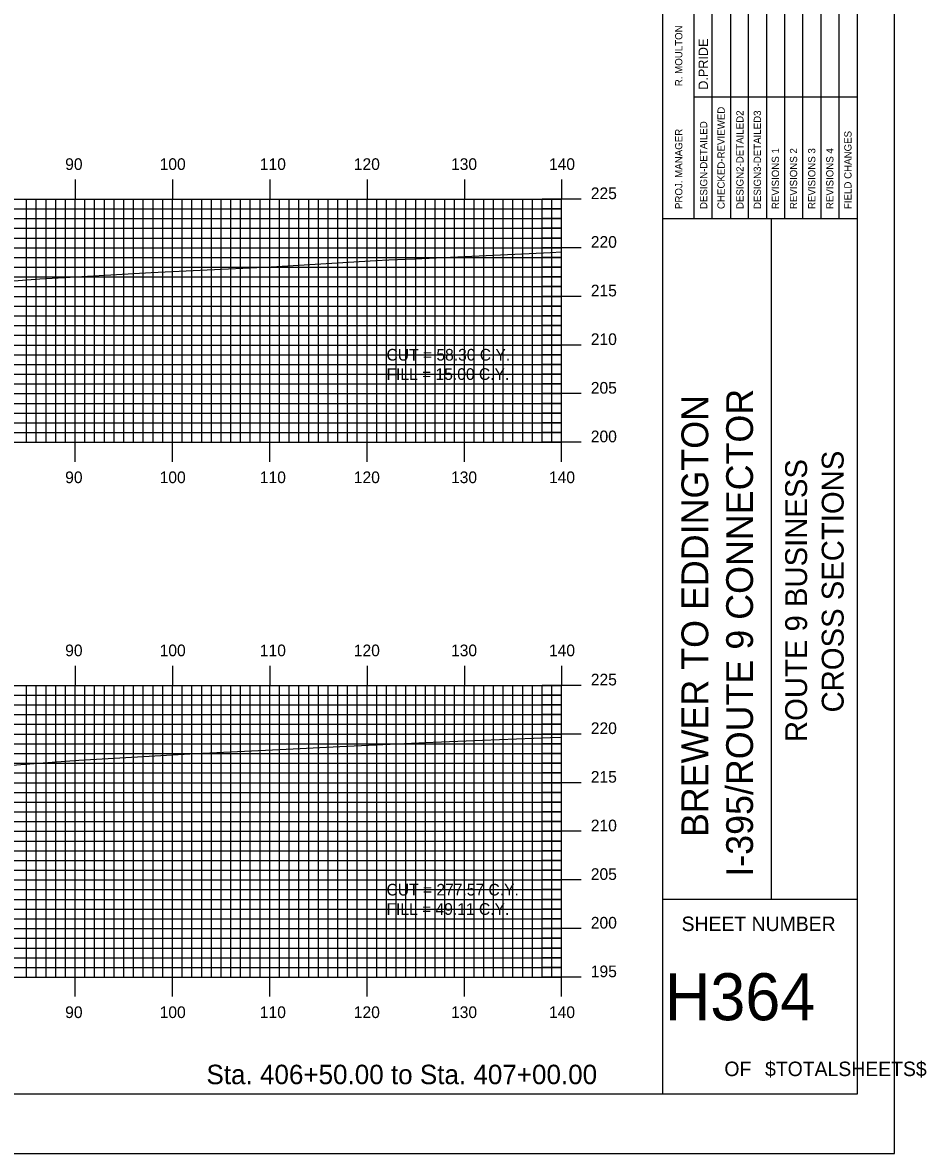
# Model space of a CAD drawing. Extents: x 852135 to 852479, y 364785 to 365005.
# Drawn here: x 852385.8 to 852478.7, y 364785.1 to 364901.4 of the extents above; entities that cross this region are included whole.
import ezdxf

# ---------------------------------------------------------------- set-up
doc = ezdxf.new("R2010")
doc.units = 0
for name, color, linetype in [('BORDER', 7, 'Continuous'), ('D_Text_Standard', 7, 'Continuous'), ('H_V ANNOTATION', 7, 'Continuous'), ('MAJOR', 7, 'Continuous'), ('MINOR', 7, 'Continuous'), ('PLOT BOUNDARY', 7, 'Continuous'), ('S_Roadway_Centerline', 7, 'Continuous')]:
    doc.layers.add(name, color=color, linetype=linetype)

msp = doc.modelspace()

# ---------------------------------------------------------------- linework, layer by layer
at = {"layer": 'BORDER'}
for p, q in [((852451.62, 364791.23), (852451.62, 365001.23)), ((852451.62, 364881.24), (852471.62, 364881.24)), ((852462.8, 364811.24), (852462.8, 364881.24)), ((852451.62, 364811.24), (852471.62, 364811.24))]:
    msp.add_line(p, q, dxfattribs=at)
msp.add_lwpolyline([(852151.62, 364791.23), (852471.62, 364791.23), (852471.62, 365001.23), (852151.62, 365001.23)], close=True, dxfattribs=at)
for points in [[(852456.71, 364881.24), (852456.71, 364916.24)], [(852458.58, 364916.24), (852458.58, 364881.24)], [(852460.44, 364881.24), (852460.44, 364916.24)], [(852462.3, 364881.24), (852462.3, 364916.24)], [(852464.17, 364881.24), (852464.17, 364916.24)], [(852466.03, 364881.24), (852466.03, 364916.24)], [(852467.89, 364881.24), (852467.89, 364916.24)], [(852469.76, 364881.24), (852469.76, 364916.24)], [(852454.85, 364881.24), (852454.85, 364914.83)], [(852454.85, 364893.74), (852471.62, 364893.74)]]:
    msp.add_lwpolyline(points, dxfattribs=at)
at = {"layer": 'MAJOR'}
for p, q in [((852391.22, 364885.24), (852391.22, 364883.23)), ((852401.22, 364885.24), (852401.22, 364883.23)), ((852411.22, 364885.24), (852411.22, 364883.23)), ((852421.22, 364885.24), (852421.22, 364883.23)), ((852431.22, 364885.24), (852431.22, 364883.23)), ((852441.22, 364885.24), (852441.22, 364883.23)), ((852301.22, 364883.23), (852441.22, 364883.23)), ((852301.22, 364883.23), (852441.22, 364883.23)), ((852391.22, 364858.23), (852391.22, 364883.23)), ((852401.22, 364858.23), (852401.22, 364883.23)), ((852411.22, 364858.23), (852411.22, 364883.23)), ((852421.22, 364858.23), (852421.22, 364883.23)), ((852431.22, 364858.23), (852431.22, 364883.23)), ((852443.22, 364883.23), (852439.21, 364883.23)), ((852441.22, 364858.23), (852441.22, 364883.23)), ((852441.22, 364858.23), (852441.22, 364883.23)), ((852301.22, 364878.23), (852441.22, 364878.23)), ((852443.22, 364878.23), (852439.21, 364878.23)), ((852301.22, 364873.23), (852441.22, 364873.23)), ((852443.22, 364873.23), (852439.21, 364873.23)), ((852301.22, 364868.23), (852441.22, 364868.23)), ((852443.22, 364868.23), (852439.21, 364868.23)), ((852301.22, 364863.23), (852441.22, 364863.23)), ((852443.22, 364863.23), (852439.21, 364863.23)), ((852301.22, 364858.23), (852441.22, 364858.23)), ((852301.22, 364858.23), (852441.22, 364858.23)), ((852391.22, 364856.23), (852391.22, 364858.23)), ((852401.22, 364856.23), (852401.22, 364858.23)), ((852411.22, 364856.23), (852411.22, 364858.23)), ((852421.22, 364856.23), (852421.22, 364858.23)), ((852431.22, 364856.23), (852431.22, 364858.23)), ((852443.22, 364858.23), (852439.21, 364858.23)), ((852441.22, 364856.23), (852441.22, 364858.23)), ((852391.22, 364835.24), (852391.22, 364833.23)), ((852401.22, 364835.24), (852401.22, 364833.23)), ((852411.22, 364835.24), (852411.22, 364833.23)), ((852421.22, 364835.24), (852421.22, 364833.23)), ((852431.22, 364835.24), (852431.22, 364833.23)), ((852441.22, 364835.24), (852441.22, 364833.23)), ((852161.22, 364833.23), (852441.22, 364833.23)), ((852161.22, 364833.23), (852441.22, 364833.23)), ((852391.22, 364803.23), (852391.22, 364833.23)), ((852401.22, 364803.23), (852401.22, 364833.23)), ((852411.22, 364803.23), (852411.22, 364833.23)), ((852421.22, 364803.23), (852421.22, 364833.23)), ((852431.22, 364803.23), (852431.22, 364833.23)), ((852443.22, 364833.23), (852439.21, 364833.23)), ((852441.22, 364803.23), (852441.22, 364833.23)), ((852441.22, 364803.23), (852441.22, 364833.23)), ((852161.22, 364828.23), (852441.22, 364828.23)), ((852443.22, 364828.23), (852439.21, 364828.23)), ((852161.22, 364823.23), (852441.22, 364823.23)), ((852443.22, 364823.23), (852439.21, 364823.23)), ((852161.22, 364818.23), (852441.22, 364818.23)), ((852443.22, 364818.23), (852439.21, 364818.23)), ((852161.22, 364813.23), (852441.22, 364813.23)), ((852443.22, 364813.23), (852439.21, 364813.23)), ((852161.22, 364808.23), (852441.22, 364808.23)), ((852443.22, 364808.23), (852439.21, 364808.23)), ((852161.22, 364803.23), (852441.22, 364803.23)), ((852161.22, 364803.23), (852441.22, 364803.23)), ((852391.22, 364801.23), (852391.22, 364803.23)), ((852401.22, 364801.23), (852401.22, 364803.23)), ((852411.22, 364801.23), (852411.22, 364803.23)), ((852421.22, 364801.23), (852421.22, 364803.23)), ((852431.22, 364801.23), (852431.22, 364803.23)), ((852443.22, 364803.23), (852439.21, 364803.23)), ((852441.22, 364801.23), (852441.22, 364803.23))]:
    msp.add_line(p, q, dxfattribs=at)
at = {"layer": 'MINOR'}
for p, q in [((852386.22, 364858.23), (852386.22, 364883.23)), ((852387.22, 364858.23), (852387.22, 364883.23)), ((852388.22, 364858.23), (852388.22, 364883.23)), ((852389.22, 364858.23), (852389.22, 364883.23)), ((852390.22, 364858.23), (852390.22, 364883.23)), ((852392.22, 364858.23), (852392.22, 364883.23)), ((852393.22, 364858.23), (852393.22, 364883.23)), ((852394.22, 364858.23), (852394.22, 364883.23)), ((852395.22, 364858.23), (852395.22, 364883.23)), ((852396.22, 364858.23), (852396.22, 364883.23)), ((852397.22, 364858.23), (852397.22, 364883.23)), ((852398.22, 364858.23), (852398.22, 364883.23)), ((852399.22, 364858.23), (852399.22, 364883.23)), ((852400.22, 364858.23), (852400.22, 364883.23)), ((852402.22, 364858.23), (852402.22, 364883.23)), ((852403.22, 364858.23), (852403.22, 364883.23)), ((852404.22, 364858.23), (852404.22, 364883.23)), ((852405.22, 364858.23), (852405.22, 364883.23)), ((852406.22, 364858.23), (852406.22, 364883.23)), ((852407.22, 364858.23), (852407.22, 364883.23)), ((852408.22, 364858.23), (852408.22, 364883.23)), ((852409.22, 364858.23), (852409.22, 364883.23)), ((852410.22, 364858.23), (852410.22, 364883.23)), ((852412.22, 364858.23), (852412.22, 364883.23)), ((852413.22, 364858.23), (852413.22, 364883.23)), ((852414.22, 364858.23), (852414.22, 364883.23)), ((852415.22, 364858.23), (852415.22, 364883.23)), ((852416.22, 364858.23), (852416.22, 364883.23)), ((852417.22, 364858.23), (852417.22, 364883.23)), ((852418.22, 364858.23), (852418.22, 364883.23)), ((852419.22, 364858.23), (852419.22, 364883.23)), ((852420.22, 364858.23), (852420.22, 364883.23)), ((852422.22, 364858.23), (852422.22, 364883.23)), ((852423.22, 364858.23), (852423.22, 364883.23)), ((852424.22, 364858.23), (852424.22, 364883.23)), ((852425.22, 364858.23), (852425.22, 364883.23)), ((852426.22, 364858.23), (852426.22, 364883.23)), ((852427.22, 364858.23), (852427.22, 364883.23)), ((852428.22, 364858.23), (852428.22, 364883.23)), ((852429.22, 364858.23), (852429.22, 364883.23)), ((852430.22, 364858.23), (852430.22, 364883.23)), ((852432.22, 364858.23), (852432.22, 364883.23)), ((852433.22, 364858.23), (852433.22, 364883.23)), ((852434.22, 364858.23), (852434.22, 364883.23)), ((852435.22, 364858.23), (852435.22, 364883.23)), ((852436.22, 364858.23), (852436.22, 364883.23)), ((852437.22, 364858.23), (852437.22, 364883.23)), ((852438.22, 364858.23), (852438.22, 364883.23)), ((852439.22, 364858.23), (852439.22, 364883.23)), ((852440.22, 364858.23), (852440.22, 364883.23)), ((852301.22, 364882.23), (852441.22, 364882.23)), ((852301.22, 364881.23), (852441.22, 364881.23)), ((852441.22, 364882.23), (852439.21, 364882.23)), ((852441.22, 364881.23), (852439.21, 364881.23)), ((852301.22, 364880.23), (852441.22, 364880.23)), ((852441.22, 364880.23), (852439.21, 364880.23)), ((852301.22, 364879.23), (852441.22, 364879.23)), ((852441.22, 364879.23), (852439.21, 364879.23)), ((852301.22, 364877.23), (852441.22, 364877.23)), ((852441.22, 364877.23), (852439.21, 364877.23)), ((852301.22, 364876.23), (852441.22, 364876.23)), ((852441.22, 364876.23), (852439.21, 364876.23)), ((852301.22, 364875.23), (852441.22, 364875.23)), ((852301.22, 364874.23), (852441.22, 364874.23)), ((852441.22, 364875.23), (852439.21, 364875.23)), ((852441.22, 364874.23), (852439.21, 364874.23)), ((852301.22, 364872.23), (852441.22, 364872.23)), ((852441.22, 364872.23), (852439.21, 364872.23)), ((852301.22, 364871.23), (852441.22, 364871.23)), ((852441.22, 364871.23), (852439.21, 364871.23)), ((852301.22, 364870.23), (852441.22, 364870.23)), ((852441.22, 364870.23), (852439.21, 364870.23)), ((852301.22, 364869.23), (852441.22, 364869.23)), ((852441.22, 364869.23), (852439.21, 364869.23)), ((852301.22, 364867.23), (852441.22, 364867.23)), ((852441.22, 364867.23), (852439.21, 364867.23)), ((852301.22, 364866.23), (852441.22, 364866.23)), ((852441.22, 364866.23), (852439.21, 364866.23)), ((852301.22, 364865.23), (852441.22, 364865.23)), ((852441.22, 364865.23), (852439.21, 364865.23)), ((852301.22, 364864.23), (852441.22, 364864.23)), ((852441.22, 364864.23), (852439.21, 364864.23)), ((852301.22, 364862.23), (852441.22, 364862.23)), ((852441.22, 364862.23), (852439.21, 364862.23)), ((852301.22, 364861.23), (852441.22, 364861.23)), ((852301.22, 364860.23), (852441.22, 364860.23)), ((852441.22, 364861.23), (852439.21, 364861.23)), ((852441.22, 364860.23), (852439.21, 364860.23)), ((852301.22, 364859.23), (852441.22, 364859.23)), ((852441.22, 364859.23), (852439.21, 364859.23)), ((852386.22, 364803.23), (852386.22, 364833.23)), ((852387.22, 364803.23), (852387.22, 364833.23)), ((852388.22, 364803.23), (852388.22, 364833.23)), ((852389.22, 364803.23), (852389.22, 364833.23)), ((852390.22, 364803.23), (852390.22, 364833.23)), ((852392.22, 364803.23), (852392.22, 364833.23)), ((852393.22, 364803.23), (852393.22, 364833.23)), ((852394.22, 364803.23), (852394.22, 364833.23)), ((852395.22, 364803.23), (852395.22, 364833.23)), ((852396.22, 364803.23), (852396.22, 364833.23)), ((852397.22, 364803.23), (852397.22, 364833.23)), ((852398.22, 364803.23), (852398.22, 364833.23)), ((852399.22, 364803.23), (852399.22, 364833.23)), ((852400.22, 364803.23), (852400.22, 364833.23)), ((852402.22, 364803.23), (852402.22, 364833.23)), ((852403.22, 364803.23), (852403.22, 364833.23)), ((852404.22, 364803.23), (852404.22, 364833.23)), ((852405.22, 364803.23), (852405.22, 364833.23)), ((852406.22, 364803.23), (852406.22, 364833.23)), ((852407.22, 364803.23), (852407.22, 364833.23)), ((852408.22, 364803.23), (852408.22, 364833.23)), ((852409.22, 364803.23), (852409.22, 364833.23)), ((852410.22, 364803.23), (852410.22, 364833.23)), ((852412.22, 364803.23), (852412.22, 364833.23)), ((852413.22, 364803.23), (852413.22, 364833.23)), ((852414.22, 364803.23), (852414.22, 364833.23)), ((852415.22, 364803.23), (852415.22, 364833.23)), ((852416.22, 364803.23), (852416.22, 364833.23)), ((852417.22, 364803.23), (852417.22, 364833.23)), ((852418.22, 364803.23), (852418.22, 364833.23)), ((852419.22, 364803.23), (852419.22, 364833.23)), ((852420.22, 364803.23), (852420.22, 364833.23)), ((852422.22, 364803.23), (852422.22, 364833.23)), ((852423.22, 364803.23), (852423.22, 364833.23)), ((852424.22, 364803.23), (852424.22, 364833.23)), ((852425.22, 364803.23), (852425.22, 364833.23)), ((852426.22, 364803.23), (852426.22, 364833.23)), ((852427.22, 364803.23), (852427.22, 364833.23)), ((852428.22, 364803.23), (852428.22, 364833.23)), ((852429.22, 364803.23), (852429.22, 364833.23)), ((852430.22, 364803.23), (852430.22, 364833.23)), ((852432.22, 364803.23), (852432.22, 364833.23)), ((852433.22, 364803.23), (852433.22, 364833.23)), ((852434.22, 364803.23), (852434.22, 364833.23)), ((852435.22, 364803.23), (852435.22, 364833.23)), ((852436.22, 364803.23), (852436.22, 364833.23)), ((852437.22, 364803.23), (852437.22, 364833.23)), ((852438.22, 364803.23), (852438.22, 364833.23)), ((852439.22, 364803.23), (852439.22, 364833.23)), ((852440.22, 364803.23), (852440.22, 364833.23)), ((852161.22, 364832.23), (852441.22, 364832.23)), ((852161.22, 364831.23), (852441.22, 364831.23)), ((852441.22, 364832.23), (852439.21, 364832.23)), ((852441.22, 364831.23), (852439.21, 364831.23)), ((852161.22, 364830.23), (852441.22, 364830.23)), ((852441.22, 364830.23), (852439.21, 364830.23)), ((852161.22, 364829.23), (852441.22, 364829.23)), ((852441.22, 364829.23), (852439.21, 364829.23)), ((852161.22, 364827.23), (852441.22, 364827.23)), ((852441.22, 364827.23), (852439.21, 364827.23)), ((852161.22, 364826.23), (852441.22, 364826.23)), ((852441.22, 364826.23), (852439.21, 364826.23)), ((852161.22, 364825.23), (852441.22, 364825.23)), ((852161.22, 364824.23), (852441.22, 364824.23)), ((852441.22, 364825.23), (852439.21, 364825.23)), ((852441.22, 364824.23), (852439.21, 364824.23)), ((852161.22, 364822.23), (852441.22, 364822.23)), ((852441.22, 364822.23), (852439.21, 364822.23)), ((852161.22, 364821.23), (852441.22, 364821.23)), ((852441.22, 364821.23), (852439.21, 364821.23)), ((852161.22, 364820.23), (852441.22, 364820.23)), ((852441.22, 364820.23), (852439.21, 364820.23)), ((852161.22, 364819.23), (852441.22, 364819.23)), ((852441.22, 364819.23), (852439.21, 364819.23)), ((852161.22, 364817.23), (852441.22, 364817.23)), ((852441.22, 364817.23), (852439.21, 364817.23)), ((852161.22, 364816.23), (852441.22, 364816.23)), ((852441.22, 364816.23), (852439.21, 364816.23)), ((852161.22, 364815.23), (852441.22, 364815.23)), ((852441.22, 364815.23), (852439.21, 364815.23)), ((852161.22, 364814.23), (852441.22, 364814.23)), ((852441.22, 364814.23), (852439.21, 364814.23)), ((852161.22, 364812.23), (852441.22, 364812.23)), ((852441.22, 364812.23), (852439.21, 364812.23)), ((852161.22, 364811.23), (852441.22, 364811.23)), ((852161.22, 364810.23), (852441.22, 364810.23)), ((852441.22, 364811.23), (852439.21, 364811.23)), ((852441.22, 364810.23), (852439.21, 364810.23)), ((852161.22, 364809.23), (852441.22, 364809.23)), ((852441.22, 364809.23), (852439.21, 364809.23)), ((852161.22, 364807.23), (852441.22, 364807.23)), ((852441.22, 364807.23), (852439.21, 364807.23)), ((852161.22, 364806.23), (852441.22, 364806.23)), ((852441.22, 364806.23), (852439.21, 364806.23)), ((852161.22, 364805.23), (852441.22, 364805.23)), ((852441.22, 364805.23), (852439.21, 364805.23)), ((852161.22, 364804.23), (852441.22, 364804.23)), ((852441.22, 364804.23), (852439.21, 364804.23))]:
    msp.add_line(p, q, dxfattribs=at)
at = {"layer": 'PLOT BOUNDARY'}
msp.add_lwpolyline([(852135.43, 364785.11), (852475.43, 364785.11), (852475.43, 365005.11), (852135.43, 365005.11)], close=True, dxfattribs=at)
at = {"layer": 'S_Roadway_Centerline'}
for points in [[(852378.05, 364874.33), (852386.25, 364874.92), (852387.6, 364875.02), (852390.13, 364875.17), (852399.03, 364875.69), (852404.08, 364875.94), (852411.35, 364876.28), (852422.11, 364876.91), (852423.47, 364876.98), (852426.13, 364877.08), (852440.06, 364877.74), (852441.22, 364877.81)], [(852382.41, 364824.87), (852391.59, 364825.55), (852395.82, 364825.8), (852403.63, 364826.23), (852414.36, 364826.75), (852415.01, 364826.79), (852418.41, 364826.94), (852428.01, 364827.4), (852433.09, 364827.59), (852440.06, 364827.86), (852441.22, 364827.92)]]:
    msp.add_lwpolyline(points, dxfattribs=at)

# ---------------------------------------------------------------- texts
at = {"layer": 'BORDER'}
for s, height, p in [('R. MOULTON', 0.745, (852453.63, 364894.84)), ('D.PRIDE', 0.969, (852456.26, 364894.48)), ('CHECKED-REVIEWED', 0.7455, (852457.98, 364882.21)), ('DESIGN2-DETAILED2', 0.7455, (852459.92, 364882.21)), ('DESIGN3-DETAILED3', 0.7455, (852461.71, 364882.21)), ('PROJ. MANAGER', 0.7455, (852453.63, 364882.21)), ('DESIGN-DETAILED', 0.7455, (852456.19, 364882.21)), ('FIELD CHANGES', 0.7455, (852471.02, 364882.21)), ('REVISIONS 1', 0.7455, (852463.57, 364882.21)), ('REVISIONS 2', 0.7455, (852465.43, 364882.21)), ('REVISIONS 3', 0.7455, (852467.3, 364882.21)), ('REVISIONS 4', 0.7455, (852469.16, 364882.21)), ('BREWER TO EDDINGTON', 2.7557, (852456.29, 364817.64)), ('I-395/ROUTE 9 CONNECTOR', 2.7557, (852460.89, 364813.56)), ('CROSS SECTIONS', 2.25, (852470.21, 364830.45)), ('ROUTE 9 BUSINESS', 2.25, (852466.45, 364827.41))]:
    msp.add_text(s, height=height, rotation=90, dxfattribs=at).set_placement(p)
for s, height, p in [('SHEET NUMBER', 1.4905, (852453.55, 364807.97)), ('H364', 4.839, (852451.83, 364798.8)), ('OF', 1.491, (852457.95, 364793.06)), ('$TOTALSHEETS$', 1.4905, (852462.13, 364793.06))]:
    msp.add_text(s, height=height, dxfattribs=at).set_placement(p)
at = {"layer": 'D_Text_Standard'}
for s, p in [('CUT = 58.30 C.Y.', (852423.22, 364866.63)), ('FILL = 15.00 C.Y.', (852423.22, 364864.64)), ('CUT = 277.57 C.Y.', (852423.22, 364811.63)), ('FILL = 49.11 C.Y.', (852423.22, 364809.64))]:
    msp.add_text(s, height=1.2, dxfattribs=at).set_placement(p)
at = {"layer": 'H_V ANNOTATION'}
for s, height, p in [('90', 1.2, (852390.19, 364886.23)), ('100', 1.2, (852399.9, 364886.23)), ('110', 1.2, (852410.2, 364886.23)), ('120', 1.2, (852419.86, 364886.23)), ('130', 1.2, (852429.85, 364886.23)), ('140', 1.2, (852439.92, 364886.23)), ('225', 1.2, (852444.22, 364883.23)), ('220', 1.2, (852444.22, 364878.23)), ('215', 1.2, (852444.22, 364873.23)), ('210', 1.2, (852444.22, 364868.23)), ('205', 1.2, (852444.22, 364863.23)), ('200', 1.2, (852444.22, 364858.23)), ('90', 1.2, (852390.19, 364854.03)), ('100', 1.2, (852399.9, 364854.03)), ('110', 1.2, (852410.2, 364854.03)), ('120', 1.2, (852419.86, 364854.03)), ('130', 1.2, (852429.85, 364854.03)), ('140', 1.2, (852439.92, 364854.03)), ('90', 1.2, (852390.19, 364836.23)), ('100', 1.2, (852399.9, 364836.23)), ('110', 1.2, (852410.2, 364836.23)), ('120', 1.2, (852419.86, 364836.23)), ('130', 1.2, (852429.85, 364836.23)), ('140', 1.2, (852439.92, 364836.23)), ('225', 1.2, (852444.22, 364833.23)), ('220', 1.2, (852444.22, 364828.23)), ('215', 1.2, (852444.22, 364823.23)), ('210', 1.2, (852444.22, 364818.23)), ('205', 1.2, (852444.22, 364813.23)), ('200', 1.2, (852444.22, 364808.23)), ('195', 1.2, (852444.22, 364803.23)), ('90', 1.2, (852390.19, 364799.03)), ('100', 1.2, (852399.9, 364799.03)), ('110', 1.2, (852410.2, 364799.03)), ('120', 1.2, (852419.86, 364799.03)), ('130', 1.2, (852429.85, 364799.03)), ('140', 1.2, (852439.92, 364799.03)), ('Sta. 406+50.00 to Sta. 407+00.00', 2.0004, (852404.71, 364792.23))]:
    msp.add_text(s, height=height, dxfattribs=at).set_placement(p)

doc.saveas('drawing.dxf')
